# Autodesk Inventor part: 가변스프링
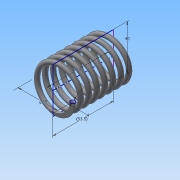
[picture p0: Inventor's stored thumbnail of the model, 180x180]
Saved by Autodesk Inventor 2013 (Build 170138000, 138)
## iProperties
Created: 2014-12
Part Number: 가변스프링
Material: 일반
Document SubType Name: Modeling
Designer: Administrator
Density: 1 g/cm^3
Mass: 10.1817 g
Surface Area: 103.216 cm^2
Volume: 10.1817 cm^3
Author: Administrator
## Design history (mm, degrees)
sketch "스케치1"
  geometry: L1 (0, 0)-(0, 48.5); L2 (0, 0)-(17.5, 0); L3 (0, 48.5)-(17.5, 48.5); C1 r 2 at (17.5, 0)
  constraints: 6 end point, 2 parallel, 1 centre point, 1 horizontal alignment, 1 perpendicular, 1 vertical
  dimensions: "d0" = 48.5 distance of L1.start L1.end (derived); "d1" = 4 diameter of C1; "d2" = 35 diameter of L2.end L1
feature "코일1" sketch "스케치1" pitch "d3" = 10; turns "d5" = 7.5; dims "d4" = 48.5 (= d0), "d6" = 0, angle "d7" = 90 deg, angle "d8" = 90 deg, "d9" = 0, "d10" = 0
sketch "스케치2"
  geometry: L1 (48.5, 20)-(0, 20); L2 (0, 20)-(0, -20); L3 (0, -20)-(48.5, -20); L4 (48.5, -20)-(48.5, 20); 2 further points
  constraints: 8 end point, 2 parallel, 1 coincident, 1 horizontal, 1 midpoint, 1 perpendicular
  dimensions: "d11" = 40 distance of L3.end L1.start; "d13" = 48.5 distance of L2.end L3.end (derived)
extrude "돌출1" sketch "스케치2" stored distance "d14" = 55; taper "d15" = 0 deg
node "솔리드1"
